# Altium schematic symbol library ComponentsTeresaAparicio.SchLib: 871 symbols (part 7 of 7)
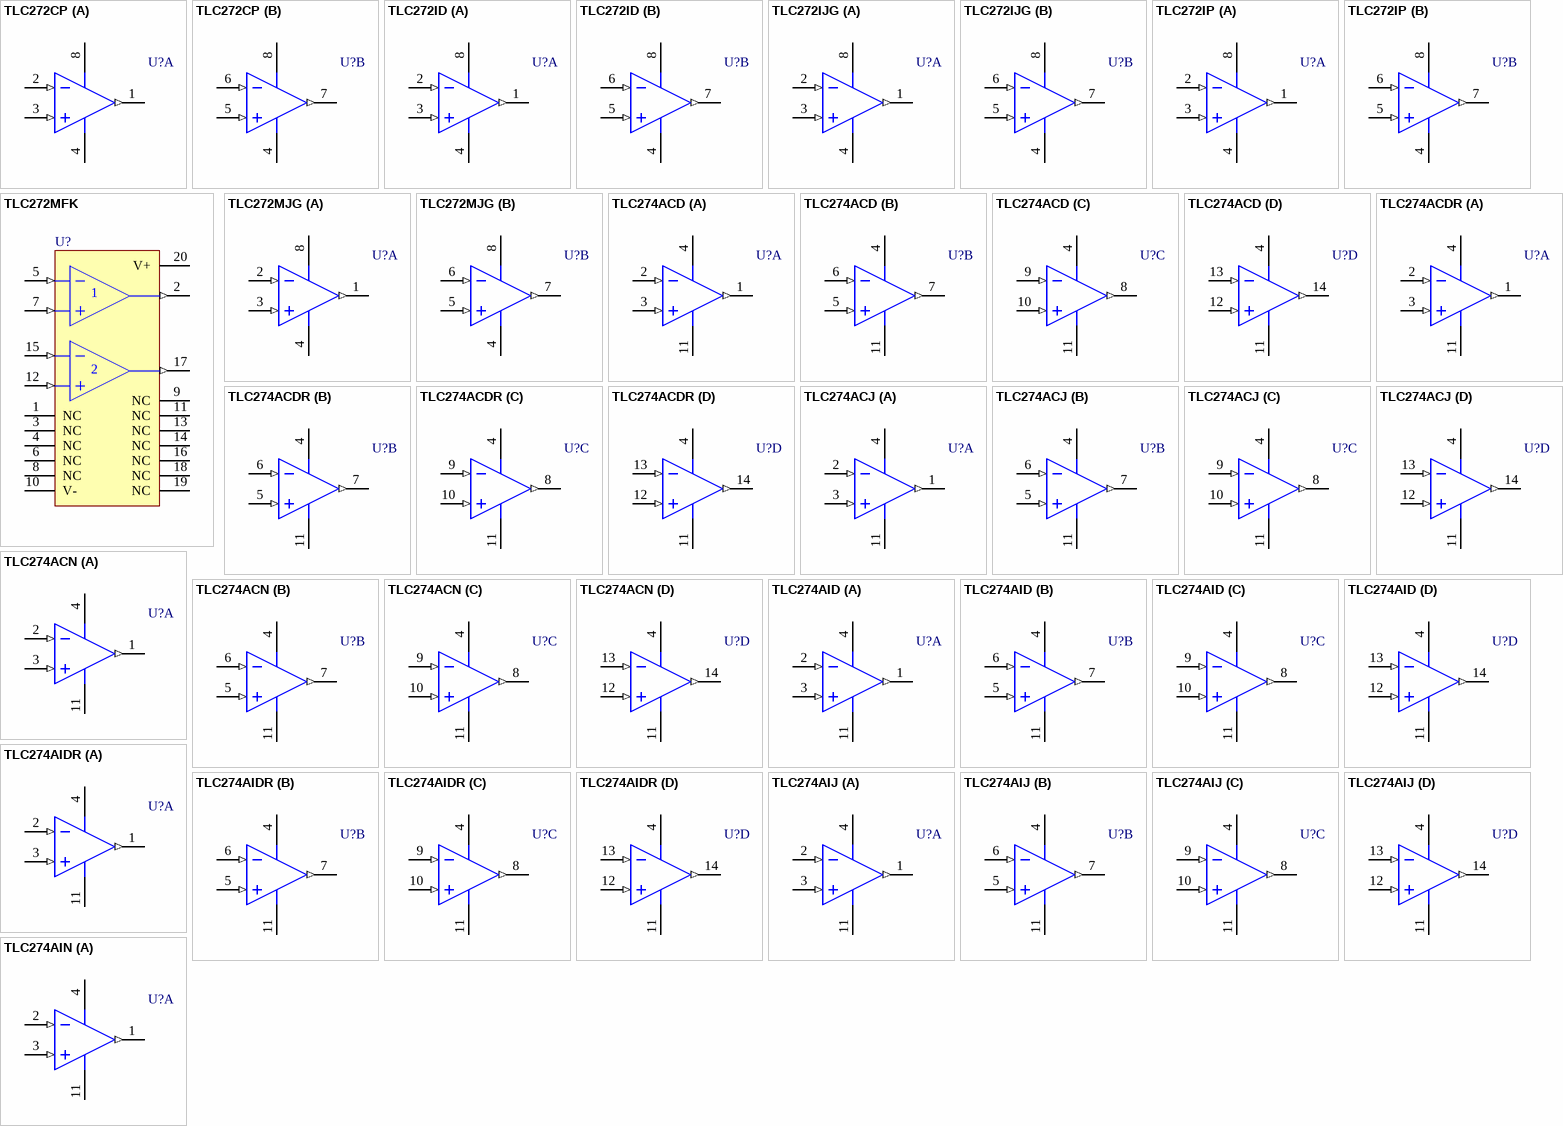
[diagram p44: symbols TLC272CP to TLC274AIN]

## TLC274AIJ
designator U?
LinCMOS Precision Quad Operational Amplifier
footprint J014 (DIP; 14 Leads; Row Spacing 7.62 mm; Pitch 2.54 mm)
3D model J014 (DIP; 14 Leads; Row Spacing 7.62 mm; Pitch 2.54 mm)
pins on every part: 4 V+ (power), 11 V- (power)
part A pins: 1 OUT (out), 2 IN- (in), 3 IN+ (in)
part B pins: 5 IN+ (in), 6 IN- (in), 7 OUT (out)
part C pins: 8 OUT (out), 9 IN- (in), 10 IN+ (in)
part D pins: 12 IN+ (in), 13 IN- (in), 14 OUT (out)

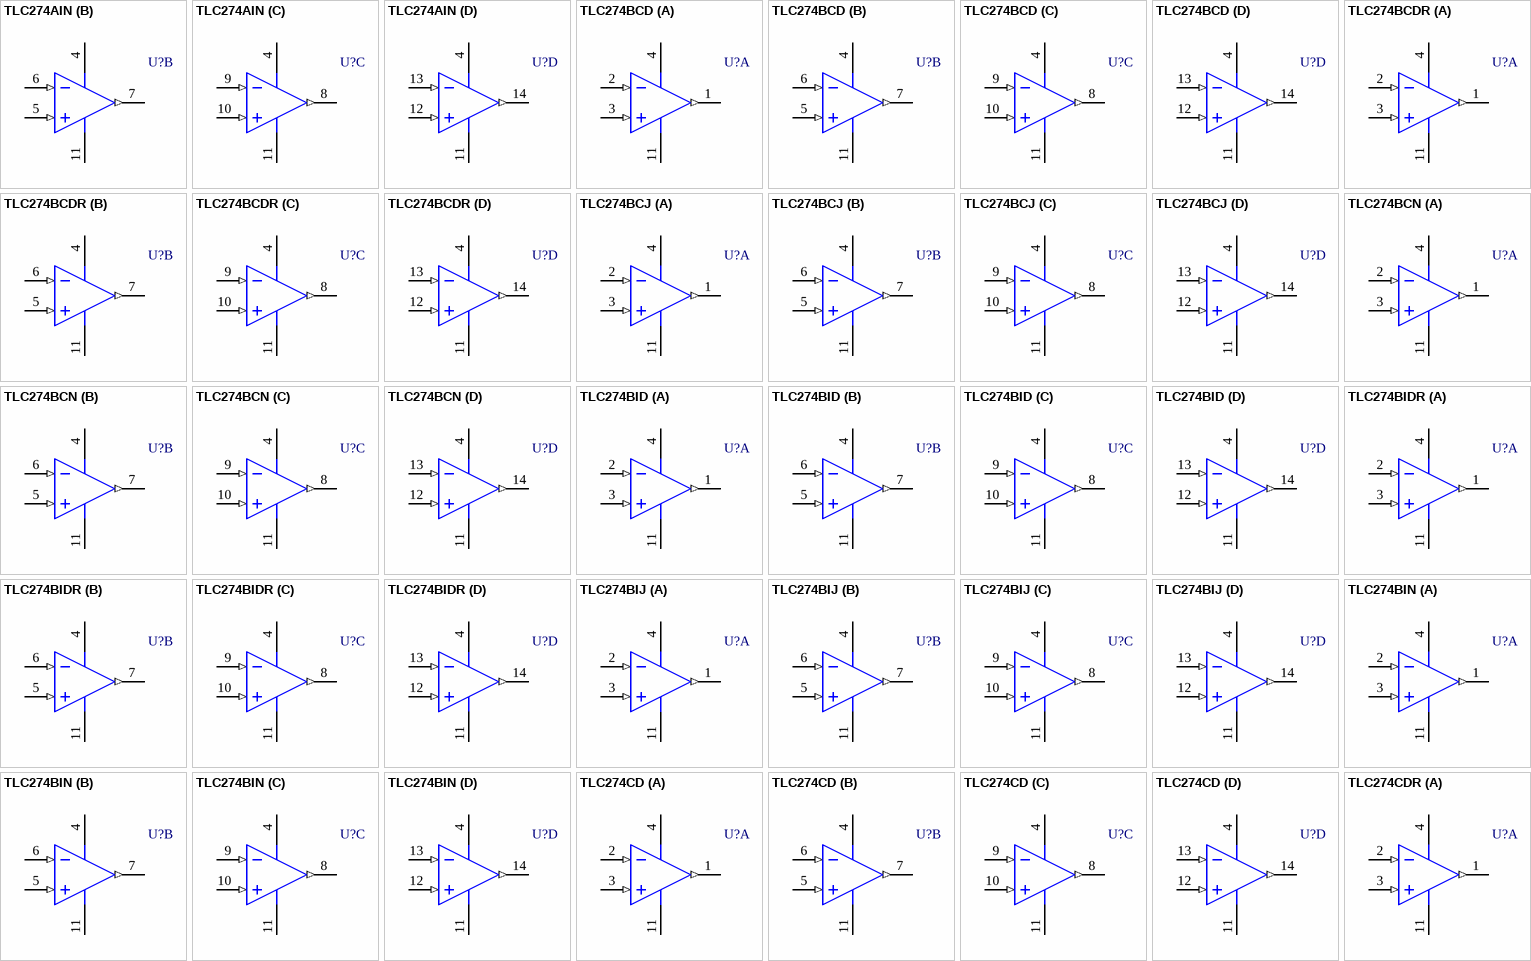
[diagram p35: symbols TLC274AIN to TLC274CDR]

## TLC274AIN
designator U?
LinCMOS Precision Quad Operational Amplifier
footprint N014 (DIP; 14 Leads; Row Spacing 7.62 mm; Pitch 2.54 mm)
3D model N014 (DIP; 14 Leads; Row Spacing 7.62 mm; Pitch 2.54 mm)
pins on every part: 4 V+ (power), 11 V- (power)
part A pins: 1 OUT (out), 2 IN- (in), 3 IN+ (in)
part B pins: 5 IN+ (in), 6 IN- (in), 7 OUT (out)
part C pins: 8 OUT (out), 9 IN- (in), 10 IN+ (in)
part D pins: 12 IN+ (in), 13 IN- (in), 14 OUT (out)

## TLC274BCD
designator U?
LinCMOS Precision Quad Operational Amplifier
footprint D014_N (SOIC, 14-Leads, Body 8.7x3.9mm, Pitch 1.27mm, IPC Medium Density)
footprint D014_L (SOIC, 14-Leads, Body 8.7x3.9mm, Pitch 1.27mm, IPC High Density)
footprint D014_M (SOIC, 14-Leads, Body 8.7x3.9mm, Pitch 1.27mm, IPC Low Density)
3D model D014 (14-Pin Small Outline Integrated Circuit 1.27 mm Pitch)
pins on every part: 4 V+ (power), 11 V- (power)
part A pins: 1 OUT (out), 2 IN- (in), 3 IN+ (in)
part B pins: 5 IN+ (in), 6 IN- (in), 7 OUT (out)
part C pins: 8 OUT (out), 9 IN- (in), 10 IN+ (in)
part D pins: 12 IN+ (in), 13 IN- (in), 14 OUT (out)

## TLC274BCDR
designator U?
LinCMOS Precision Quad Operational Amplifier
footprint D014_N (SOIC, 14-Leads, Body 8.7x3.9mm, Pitch 1.27mm, IPC Medium Density)
footprint D014_L (SOIC, 14-Leads, Body 8.7x3.9mm, Pitch 1.27mm, IPC High Density)
footprint D014_M (SOIC, 14-Leads, Body 8.7x3.9mm, Pitch 1.27mm, IPC Low Density)
3D model D014 (14-Pin Small Outline Integrated Circuit 1.27 mm Pitch)
pins on every part: 4 V+ (power), 11 V- (power)
part A pins: 1 OUT (out), 2 IN- (in), 3 IN+ (in)
part B pins: 5 IN+ (in), 6 IN- (in), 7 OUT (out)
part C pins: 8 OUT (out), 9 IN- (in), 10 IN+ (in)
part D pins: 12 IN+ (in), 13 IN- (in), 14 OUT (out)

## TLC274BCJ
designator U?
LinCMOS Precision Quad Operational Amplifier
footprint J014 (DIP; 14 Leads; Row Spacing 7.62 mm; Pitch 2.54 mm)
3D model J014 (DIP; 14 Leads; Row Spacing 7.62 mm; Pitch 2.54 mm)
pins on every part: 4 V+ (power), 11 V- (power)
part A pins: 1 OUT (out), 2 IN- (in), 3 IN+ (in)
part B pins: 5 IN+ (in), 6 IN- (in), 7 OUT (out)
part C pins: 8 OUT (out), 9 IN- (in), 10 IN+ (in)
part D pins: 12 IN+ (in), 13 IN- (in), 14 OUT (out)

## TLC274BCN
designator U?
LinCMOS Precision Quad Operational Amplifier
footprint N014 (DIP; 14 Leads; Row Spacing 7.62 mm; Pitch 2.54 mm)
3D model N014 (DIP; 14 Leads; Row Spacing 7.62 mm; Pitch 2.54 mm)
pins on every part: 4 V+ (power), 11 V- (power)
part A pins: 1 OUT (out), 2 IN- (in), 3 IN+ (in)
part B pins: 5 IN+ (in), 6 IN- (in), 7 OUT (out)
part C pins: 8 OUT (out), 9 IN- (in), 10 IN+ (in)
part D pins: 12 IN+ (in), 13 IN- (in), 14 OUT (out)

## TLC274BID
designator U?
LinCMOS Precision Quad Operational Amplifier
footprint D014_N (SOIC, 14-Leads, Body 8.7x3.9mm, Pitch 1.27mm, IPC Medium Density)
footprint D014_L (SOIC, 14-Leads, Body 8.7x3.9mm, Pitch 1.27mm, IPC High Density)
footprint D014_M (SOIC, 14-Leads, Body 8.7x3.9mm, Pitch 1.27mm, IPC Low Density)
3D model D014 (14-Pin Small Outline Integrated Circuit 1.27 mm Pitch)
pins on every part: 4 V+ (power), 11 V- (power)
part A pins: 1 OUT (out), 2 IN- (in), 3 IN+ (in)
part B pins: 5 IN+ (in), 6 IN- (in), 7 OUT (out)
part C pins: 8 OUT (out), 9 IN- (in), 10 IN+ (in)
part D pins: 12 IN+ (in), 13 IN- (in), 14 OUT (out)

## TLC274BIDR
designator U?
LinCMOS Precision Quad Operational Amplifier
footprint D014_N (SOIC, 14-Leads, Body 8.7x3.9mm, Pitch 1.27mm, IPC Medium Density)
footprint D014_L (SOIC, 14-Leads, Body 8.7x3.9mm, Pitch 1.27mm, IPC High Density)
footprint D014_M (SOIC, 14-Leads, Body 8.7x3.9mm, Pitch 1.27mm, IPC Low Density)
3D model D014 (14-Pin Small Outline Integrated Circuit 1.27 mm Pitch)
pins on every part: 4 V+ (power), 11 V- (power)
part A pins: 1 OUT (out), 2 IN- (in), 3 IN+ (in)
part B pins: 5 IN+ (in), 6 IN- (in), 7 OUT (out)
part C pins: 8 OUT (out), 9 IN- (in), 10 IN+ (in)
part D pins: 12 IN+ (in), 13 IN- (in), 14 OUT (out)

## TLC274BIJ
designator U?
LinCMOS Precision Quad Operational Amplifier
footprint J014 (DIP; 14 Leads; Row Spacing 7.62 mm; Pitch 2.54 mm)
3D model J014 (DIP; 14 Leads; Row Spacing 7.62 mm; Pitch 2.54 mm)
pins on every part: 4 V+ (power), 11 V- (power)
part A pins: 1 OUT (out), 2 IN- (in), 3 IN+ (in)
part B pins: 5 IN+ (in), 6 IN- (in), 7 OUT (out)
part C pins: 8 OUT (out), 9 IN- (in), 10 IN+ (in)
part D pins: 12 IN+ (in), 13 IN- (in), 14 OUT (out)

## TLC274BIN
designator U?
LinCMOS Precision Quad Operational Amplifier
footprint N014 (DIP; 14 Leads; Row Spacing 7.62 mm; Pitch 2.54 mm)
3D model N014 (DIP; 14 Leads; Row Spacing 7.62 mm; Pitch 2.54 mm)
pins on every part: 4 V+ (power), 11 V- (power)
part A pins: 1 OUT (out), 2 IN- (in), 3 IN+ (in)
part B pins: 5 IN+ (in), 6 IN- (in), 7 OUT (out)
part C pins: 8 OUT (out), 9 IN- (in), 10 IN+ (in)
part D pins: 12 IN+ (in), 13 IN- (in), 14 OUT (out)

## TLC274CD
designator U?
LinCMOS Precision Quad Operational Amplifier
footprint D014_N (SOIC, 14-Leads, Body 8.7x3.9mm, Pitch 1.27mm, IPC Medium Density)
footprint D014_L (SOIC, 14-Leads, Body 8.7x3.9mm, Pitch 1.27mm, IPC High Density)
footprint D014_M (SOIC, 14-Leads, Body 8.7x3.9mm, Pitch 1.27mm, IPC Low Density)
3D model D014 (14-Pin Small Outline Integrated Circuit 1.27 mm Pitch)
pins on every part: 4 V+ (power), 11 V- (power)
part A pins: 1 OUT (out), 2 IN- (in), 3 IN+ (in)
part B pins: 5 IN+ (in), 6 IN- (in), 7 OUT (out)
part C pins: 8 OUT (out), 9 IN- (in), 10 IN+ (in)
part D pins: 12 IN+ (in), 13 IN- (in), 14 OUT (out)

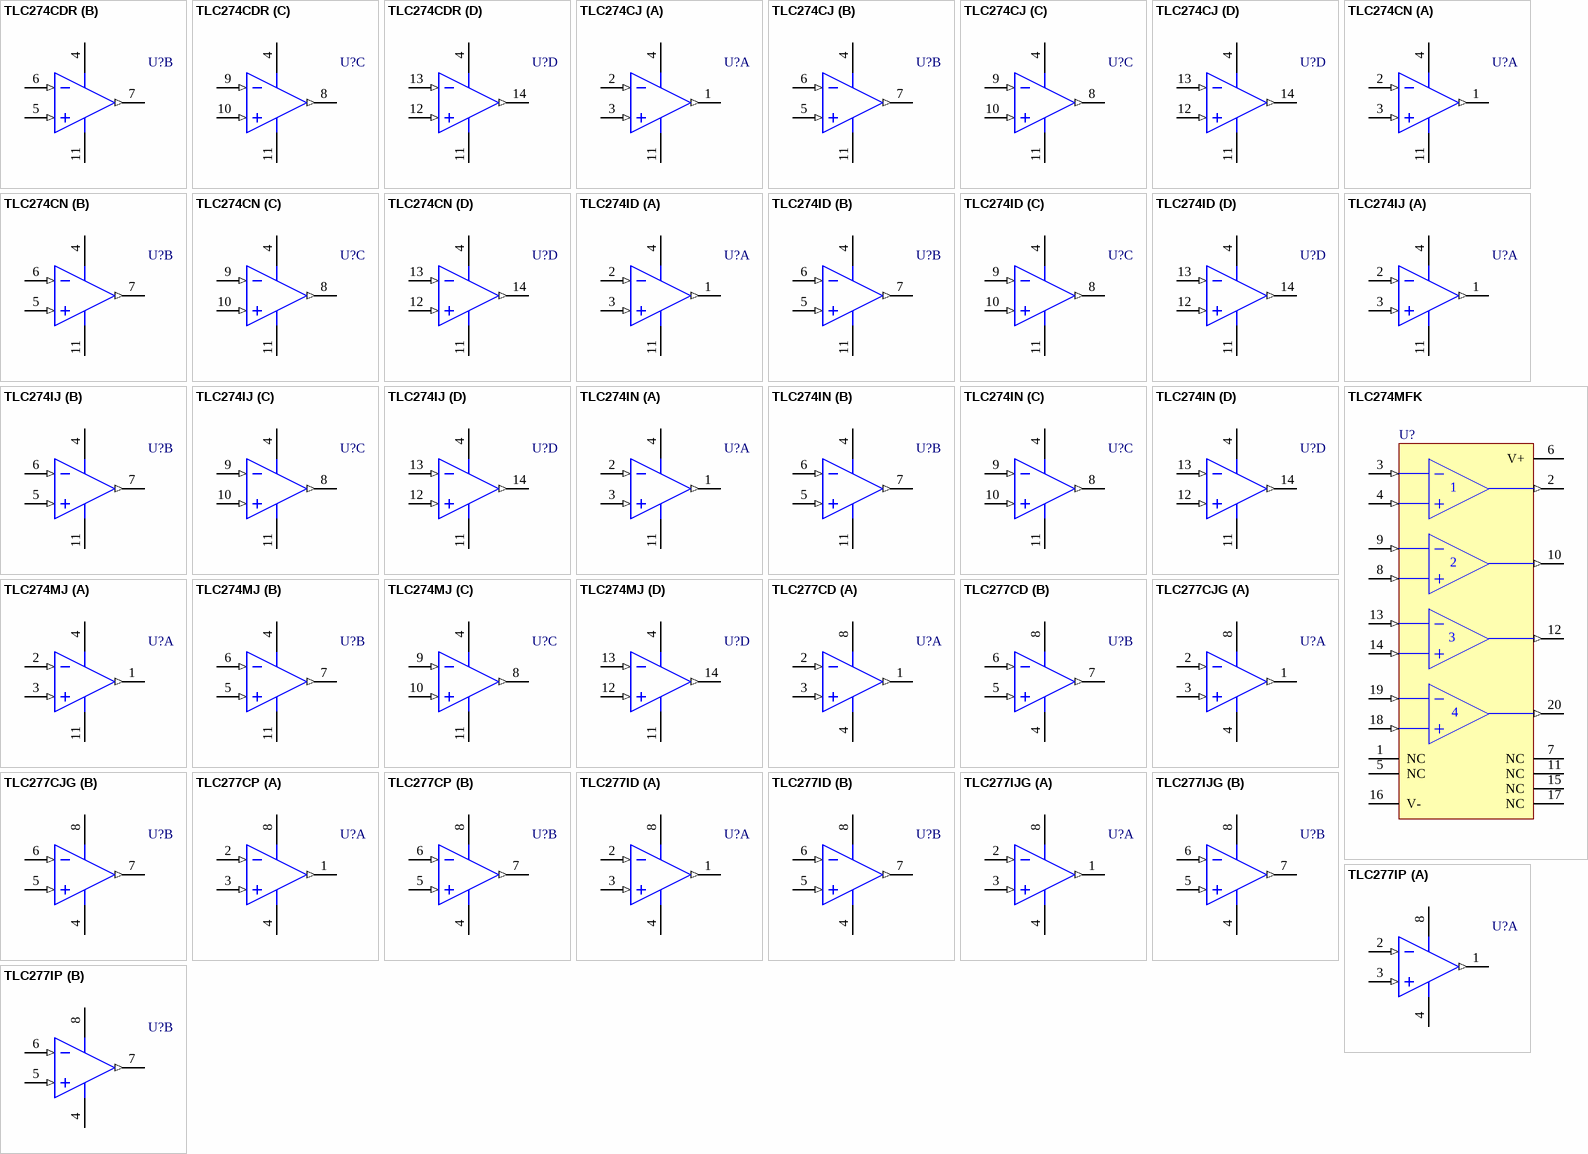
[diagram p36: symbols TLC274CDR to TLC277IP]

## TLC274CDR
designator U?
LinCMOS Precision Quad Operational Amplifier
footprint D014_N (SOIC, 14-Leads, Body 8.7x3.9mm, Pitch 1.27mm, IPC Medium Density)
footprint D014_L (SOIC, 14-Leads, Body 8.7x3.9mm, Pitch 1.27mm, IPC High Density)
footprint D014_M (SOIC, 14-Leads, Body 8.7x3.9mm, Pitch 1.27mm, IPC Low Density)
3D model D014 (14-Pin Small Outline Integrated Circuit 1.27 mm Pitch)
pins on every part: 4 V+ (power), 11 V- (power)
part A pins: 1 OUT (out), 2 IN- (in), 3 IN+ (in)
part B pins: 5 IN+ (in), 6 IN- (in), 7 OUT (out)
part C pins: 8 OUT (out), 9 IN- (in), 10 IN+ (in)
part D pins: 12 IN+ (in), 13 IN- (in), 14 OUT (out)

## TLC274CJ
designator U?
LinCMOS Precision Quad Operational Amplifier
footprint J014 (DIP; 14 Leads; Row Spacing 7.62 mm; Pitch 2.54 mm)
3D model J014 (DIP; 14 Leads; Row Spacing 7.62 mm; Pitch 2.54 mm)
pins on every part: 4 V+ (power), 11 V- (power)
part A pins: 1 OUT (out), 2 IN- (in), 3 IN+ (in)
part B pins: 5 IN+ (in), 6 IN- (in), 7 OUT (out)
part C pins: 8 OUT (out), 9 IN- (in), 10 IN+ (in)
part D pins: 12 IN+ (in), 13 IN- (in), 14 OUT (out)

## TLC274CN
designator U?
LinCMOS Precision Quad Operational Amplifier
footprint N014 (DIP; 14 Leads; Row Spacing 7.62 mm; Pitch 2.54 mm)
3D model N014 (DIP; 14 Leads; Row Spacing 7.62 mm; Pitch 2.54 mm)
pins on every part: 4 V+ (power), 11 V- (power)
part A pins: 1 OUT (out), 2 IN- (in), 3 IN+ (in)
part B pins: 5 IN+ (in), 6 IN- (in), 7 OUT (out)
part C pins: 8 OUT (out), 9 IN- (in), 10 IN+ (in)
part D pins: 12 IN+ (in), 13 IN- (in), 14 OUT (out)

## TLC274ID
designator U?
LinCMOS Precision Quad Operational Amplifier
footprint D014_N (SOIC, 14-Leads, Body 8.7x3.9mm, Pitch 1.27mm, IPC Medium Density)
footprint D014_L (SOIC, 14-Leads, Body 8.7x3.9mm, Pitch 1.27mm, IPC High Density)
footprint D014_M (SOIC, 14-Leads, Body 8.7x3.9mm, Pitch 1.27mm, IPC Low Density)
3D model D014 (14-Pin Small Outline Integrated Circuit 1.27 mm Pitch)
pins on every part: 4 V+ (power), 11 V- (power)
part A pins: 1 OUT (out), 2 IN- (in), 3 IN+ (in)
part B pins: 5 IN+ (in), 6 IN- (in), 7 OUT (out)
part C pins: 8 OUT (out), 9 IN- (in), 10 IN+ (in)
part D pins: 12 IN+ (in), 13 IN- (in), 14 OUT (out)

## TLC274IJ
designator U?
LinCMOS Precision Quad Operational Amplifier
footprint J014 (DIP; 14 Leads; Row Spacing 7.62 mm; Pitch 2.54 mm)
3D model J014 (DIP; 14 Leads; Row Spacing 7.62 mm; Pitch 2.54 mm)
pins on every part: 4 V+ (power), 11 V- (power)
part A pins: 1 OUT (out), 2 IN- (in), 3 IN+ (in)
part B pins: 5 IN+ (in), 6 IN- (in), 7 OUT (out)
part C pins: 8 OUT (out), 9 IN- (in), 10 IN+ (in)
part D pins: 12 IN+ (in), 13 IN- (in), 14 OUT (out)

## TLC274IN
designator U?
LinCMOS Precision Quad Operational Amplifier
footprint N014 (DIP; 14 Leads; Row Spacing 7.62 mm; Pitch 2.54 mm)
3D model N014 (DIP; 14 Leads; Row Spacing 7.62 mm; Pitch 2.54 mm)
pins on every part: 4 V+ (power), 11 V- (power)
part A pins: 1 OUT (out), 2 IN- (in), 3 IN+ (in)
part B pins: 5 IN+ (in), 6 IN- (in), 7 OUT (out)
part C pins: 8 OUT (out), 9 IN- (in), 10 IN+ (in)
part D pins: 12 IN+ (in), 13 IN- (in), 14 OUT (out)

## TLC274MFK
designator U?
LinCMOS Precision Quad Operational Amplifier; ComponentAvailability: Obsolete
footprint FK020 (Leadless Chip Carrier; 20 Terminals; Body 8.9 x 8.9 mm)
pins: 1 NC, 2 OUT (out), 3 IN- (in), 4 IN+ (in), 5 NC, 6 V+ (power), 7 NC, 8 IN+ (in), 9 IN- (in), 10 OUT (out), 11 NC, 12 OUT (out), 13 IN- (in), 14 IN+ (in), 15 NC, 16 V- (power), 17 NC, 18 IN+ (in), 19 IN- (in), 20 OUT (out)

## TLC274MJ
designator U?
LinCMOS Precision Quad Operational Amplifier; ComponentAvailability: Obsolete
footprint J014 (DIP; 14 Leads; Row Spacing 7.62 mm; Pitch 2.54 mm)
3D model J014 (DIP; 14 Leads; Row Spacing 7.62 mm; Pitch 2.54 mm)
pins on every part: 4 V+ (power), 11 V- (power)
part A pins: 1 OUT (out), 2 IN- (in), 3 IN+ (in)
part B pins: 5 IN+ (in), 6 IN- (in), 7 OUT (out)
part C pins: 8 OUT (out), 9 IN- (in), 10 IN+ (in)
part D pins: 12 IN+ (in), 13 IN- (in), 14 OUT (out)

## TLC277CD
designator U?
LinCMOS Precision Dual Operational Amplifier
footprint D008_L (SOIC, 8-Leads, Body 4.9x3.9mm, Pitch 1.27mm, IPC High Density)
footprint D008_M (SOIC, 8-Leads, Body 4.9x3.9mm, Pitch 1.27mm, IPC Low Density)
footprint D008_M (SOIC, 8-Leads, Body 4.9x3.9mm, Pitch 1.27mm, IPC Low Density)
3D model D008 (8-Pin Small Outline Integrated Circuit 1.27 mm Pitch)
pins on every part: 4 GND (power), 8 VDD (power)
part A pins: 1 OUT (out), 2 IN- (in), 3 IN+ (in)
part B pins: 5 IN+ (in), 6 IN- (in), 7 OUT (out)

## TLC277CJG
designator U?
LinCMOS Precision Dual Operational Amplifier
footprint JG008 (DIP; 8 Leads; Row Spacing 7.62 mm; Pitch 2.54 mm)
3D model JG008 (DIP; 8 Leads; Row Spacing 7.62 mm; Pitch 2.54 mm)
pins on every part: 4 GND (power), 8 VDD (power)
part A pins: 1 OUT (out), 2 IN- (in), 3 IN+ (in)
part B pins: 5 IN+ (in), 6 IN- (in), 7 OUT (out)

## TLC277CP
designator U?
LinCMOS Precision Dual Operational Amplifier
footprint P008 (DIP; 8 Leads; Row Spacing 7.62 mm; Pitch 2.54 mm)
3D model P008 (DIP; 8 Leads; Row Spacing 7.62 mm; Pitch 2.54 mm)
pins on every part: 4 GND (power), 8 VDD (power)
part A pins: 1 OUT (out), 2 IN- (in), 3 IN+ (in)
part B pins: 5 IN+ (in), 6 IN- (in), 7 OUT (out)

## TLC277ID
designator U?
LinCMOS Precision Dual Operational Amplifier
footprint D008_L (SOIC, 8-Leads, Body 4.9x3.9mm, Pitch 1.27mm, IPC High Density)
footprint D008_M (SOIC, 8-Leads, Body 4.9x3.9mm, Pitch 1.27mm, IPC Low Density)
footprint D008_M (SOIC, 8-Leads, Body 4.9x3.9mm, Pitch 1.27mm, IPC Low Density)
3D model D008 (8-Pin Small Outline Integrated Circuit 1.27 mm Pitch)
pins on every part: 4 GND (power), 8 VDD (power)
part A pins: 1 OUT (out), 2 IN- (in), 3 IN+ (in)
part B pins: 5 IN+ (in), 6 IN- (in), 7 OUT (out)

## TLC277IJG
designator U?
LinCMOS Precision Dual Operational Amplifier
footprint JG008 (DIP; 8 Leads; Row Spacing 7.62 mm; Pitch 2.54 mm)
3D model JG008 (DIP; 8 Leads; Row Spacing 7.62 mm; Pitch 2.54 mm)
pins on every part: 4 GND (power), 8 VDD (power)
part A pins: 1 OUT (out), 2 IN- (in), 3 IN+ (in)
part B pins: 5 IN+ (in), 6 IN- (in), 7 OUT (out)

## TLC277IP
designator U?
LinCMOS Precision Dual Operational Amplifier
footprint P008 (DIP; 8 Leads; Row Spacing 7.62 mm; Pitch 2.54 mm)
3D model P008 (DIP; 8 Leads; Row Spacing 7.62 mm; Pitch 2.54 mm)
pins on every part: 4 GND (power), 8 VDD (power)
part A pins: 1 OUT (out), 2 IN- (in), 3 IN+ (in)
part B pins: 5 IN+ (in), 6 IN- (in), 7 OUT (out)

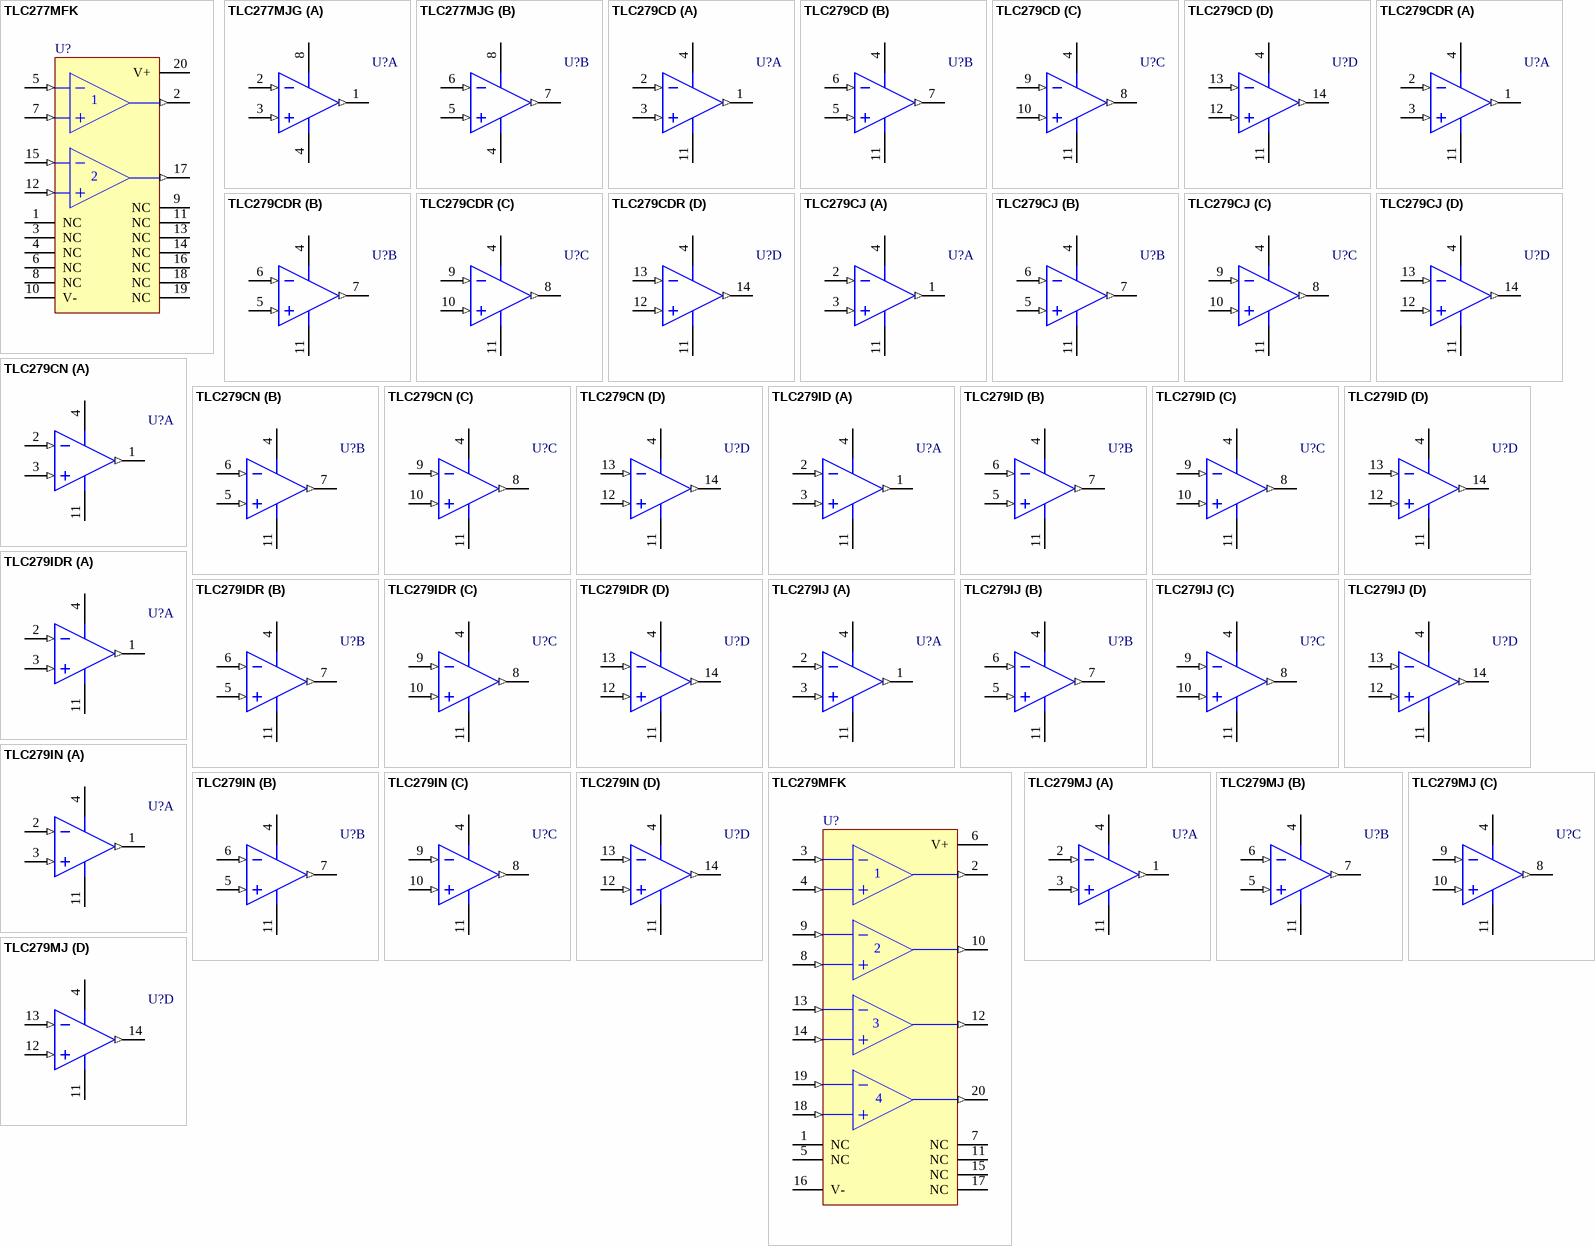
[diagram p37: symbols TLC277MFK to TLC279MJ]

## TLC277MFK
designator U?
LinCMOS Precision Quad Operational Amplifier; ComponentAvailability: Obsolete
footprint FK020 (Leadless Chip Carrier; 20 Terminals; Body 8.9 x 8.9 mm)
pins: 1 NC, 2 OUT (out), 3 NC, 4 NC, 5 IN- (in), 6 NC, 7 IN+ (in), 8 NC, 9 NC, 10 V- (power), 11 NC, 12 IN+ (in), 13 NC, 14 NC, 15 IN- (in), 16 NC, 17 OUT (out), 18 NC, 19 NC, 20 V+ (power)

## TLC277MJG
designator U?
LinCMOS Precision Dual Operational Amplifier; ComponentAvailability: Obsolete
footprint JG008 (DIP; 8 Leads; Row Spacing 7.62 mm; Pitch 2.54 mm)
3D model JG008 (DIP; 8 Leads; Row Spacing 7.62 mm; Pitch 2.54 mm)
pins on every part: 4 GND (power), 8 VDD (power)
part A pins: 1 OUT (out), 2 IN- (in), 3 IN+ (in)
part B pins: 5 IN+ (in), 6 IN- (in), 7 OUT (out)

## TLC279CD
designator U?
LinCMOS Precision Quad Operational Amplifier
footprint D014_N (SOIC, 14-Leads, Body 8.7x3.9mm, Pitch 1.27mm, IPC Medium Density)
footprint D014_L (SOIC, 14-Leads, Body 8.7x3.9mm, Pitch 1.27mm, IPC High Density)
footprint D014_M (SOIC, 14-Leads, Body 8.7x3.9mm, Pitch 1.27mm, IPC Low Density)
3D model D014 (14-Pin Small Outline Integrated Circuit 1.27 mm Pitch)
pins on every part: 4 V+ (power), 11 V- (power)
part A pins: 1 OUT (out), 2 IN- (in), 3 IN+ (in)
part B pins: 5 IN+ (in), 6 IN- (in), 7 OUT (out)
part C pins: 8 OUT (out), 9 IN- (in), 10 IN+ (in)
part D pins: 12 IN+ (in), 13 IN- (in), 14 OUT (out)

## TLC279CDR
designator U?
LinCMOS Precision Quad Operational Amplifier
footprint D014_N (SOIC, 14-Leads, Body 8.7x3.9mm, Pitch 1.27mm, IPC Medium Density)
footprint D014_L (SOIC, 14-Leads, Body 8.7x3.9mm, Pitch 1.27mm, IPC High Density)
footprint D014_M (SOIC, 14-Leads, Body 8.7x3.9mm, Pitch 1.27mm, IPC Low Density)
3D model D014 (14-Pin Small Outline Integrated Circuit 1.27 mm Pitch)
pins on every part: 4 V+ (power), 11 V- (power)
part A pins: 1 OUT (out), 2 IN- (in), 3 IN+ (in)
part B pins: 5 IN+ (in), 6 IN- (in), 7 OUT (out)
part C pins: 8 OUT (out), 9 IN- (in), 10 IN+ (in)
part D pins: 12 IN+ (in), 13 IN- (in), 14 OUT (out)

## TLC279CJ
designator U?
LinCMOS Precision Quad Operational Amplifier
footprint J014 (DIP; 14 Leads; Row Spacing 7.62 mm; Pitch 2.54 mm)
3D model J014 (DIP; 14 Leads; Row Spacing 7.62 mm; Pitch 2.54 mm)
pins on every part: 4 V+ (power), 11 V- (power)
part A pins: 1 OUT (out), 2 IN- (in), 3 IN+ (in)
part B pins: 5 IN+ (in), 6 IN- (in), 7 OUT (out)
part C pins: 8 OUT (out), 9 IN- (in), 10 IN+ (in)
part D pins: 12 IN+ (in), 13 IN- (in), 14 OUT (out)

## TLC279CN
designator U?
LinCMOS Precision Quad Operational Amplifier
footprint N014 (DIP; 14 Leads; Row Spacing 7.62 mm; Pitch 2.54 mm)
3D model N014 (DIP; 14 Leads; Row Spacing 7.62 mm; Pitch 2.54 mm)
pins on every part: 4 V+ (power), 11 V- (power)
part A pins: 1 OUT (out), 2 IN- (in), 3 IN+ (in)
part B pins: 5 IN+ (in), 6 IN- (in), 7 OUT (out)
part C pins: 8 OUT (out), 9 IN- (in), 10 IN+ (in)
part D pins: 12 IN+ (in), 13 IN- (in), 14 OUT (out)

## TLC279ID
designator U?
LinCMOS Precision Quad Operational Amplifier
footprint D014_N (SOIC, 14-Leads, Body 8.7x3.9mm, Pitch 1.27mm, IPC Medium Density)
footprint D014_L (SOIC, 14-Leads, Body 8.7x3.9mm, Pitch 1.27mm, IPC High Density)
footprint D014_M (SOIC, 14-Leads, Body 8.7x3.9mm, Pitch 1.27mm, IPC Low Density)
3D model D014 (14-Pin Small Outline Integrated Circuit 1.27 mm Pitch)
pins on every part: 4 V+ (power), 11 V- (power)
part A pins: 1 OUT (out), 2 IN- (in), 3 IN+ (in)
part B pins: 5 IN+ (in), 6 IN- (in), 7 OUT (out)
part C pins: 8 OUT (out), 9 IN- (in), 10 IN+ (in)
part D pins: 12 IN+ (in), 13 IN- (in), 14 OUT (out)

## TLC279IDR
designator U?
LinCMOS Precision Quad Operational Amplifier
footprint D014_N (SOIC, 14-Leads, Body 8.7x3.9mm, Pitch 1.27mm, IPC Medium Density)
footprint D014_L (SOIC, 14-Leads, Body 8.7x3.9mm, Pitch 1.27mm, IPC High Density)
footprint D014_M (SOIC, 14-Leads, Body 8.7x3.9mm, Pitch 1.27mm, IPC Low Density)
3D model D014 (14-Pin Small Outline Integrated Circuit 1.27 mm Pitch)
pins on every part: 4 V+ (power), 11 V- (power)
part A pins: 1 OUT (out), 2 IN- (in), 3 IN+ (in)
part B pins: 5 IN+ (in), 6 IN- (in), 7 OUT (out)
part C pins: 8 OUT (out), 9 IN- (in), 10 IN+ (in)
part D pins: 12 IN+ (in), 13 IN- (in), 14 OUT (out)

## TLC279IJ
designator U?
LinCMOS Precision Quad Operational Amplifier
footprint J014 (DIP; 14 Leads; Row Spacing 7.62 mm; Pitch 2.54 mm)
3D model J014 (DIP; 14 Leads; Row Spacing 7.62 mm; Pitch 2.54 mm)
pins on every part: 4 V+ (power), 11 V- (power)
part A pins: 1 OUT (out), 2 IN- (in), 3 IN+ (in)
part B pins: 5 IN+ (in), 6 IN- (in), 7 OUT (out)
part C pins: 8 OUT (out), 9 IN- (in), 10 IN+ (in)
part D pins: 12 IN+ (in), 13 IN- (in), 14 OUT (out)

## TLC279IN
designator U?
LinCMOS Precision Quad Operational Amplifier
footprint N014 (DIP; 14 Leads; Row Spacing 7.62 mm; Pitch 2.54 mm)
3D model N014 (DIP; 14 Leads; Row Spacing 7.62 mm; Pitch 2.54 mm)
pins on every part: 4 V+ (power), 11 V- (power)
part A pins: 1 OUT (out), 2 IN- (in), 3 IN+ (in)
part B pins: 5 IN+ (in), 6 IN- (in), 7 OUT (out)
part C pins: 8 OUT (out), 9 IN- (in), 10 IN+ (in)
part D pins: 12 IN+ (in), 13 IN- (in), 14 OUT (out)

## TLC279MFK
designator U?
LinCMOS Precision Quad Operational Amplifier; ComponentAvailability: Obsolete
footprint FK020 (Leadless Chip Carrier; 20 Terminals; Body 8.9 x 8.9 mm)
pins: 1 NC, 2 OUT (out), 3 IN- (in), 4 IN+ (in), 5 NC, 6 V+ (power), 7 NC, 8 IN+ (in), 9 IN- (in), 10 OUT (out), 11 NC, 12 OUT (out), 13 IN- (in), 14 IN+ (in), 15 NC, 16 V- (power), 17 NC, 18 IN+ (in), 19 IN- (in), 20 OUT (out)

## TLC279MJ
designator U?
LinCMOS Precision Quad Operational Amplifier; ComponentAvailability: Obsolete
footprint J014 (DIP; 14 Leads; Row Spacing 7.62 mm; Pitch 2.54 mm)
3D model J014 (DIP; 14 Leads; Row Spacing 7.62 mm; Pitch 2.54 mm)
pins on every part: 4 V+ (power), 11 V- (power)
part A pins: 1 OUT (out), 2 IN- (in), 3 IN+ (in)
part B pins: 5 IN+ (in), 6 IN- (in), 7 OUT (out)
part C pins: 8 OUT (out), 9 IN- (in), 10 IN+ (in)
part D pins: 12 IN+ (in), 13 IN- (in), 14 OUT (out)

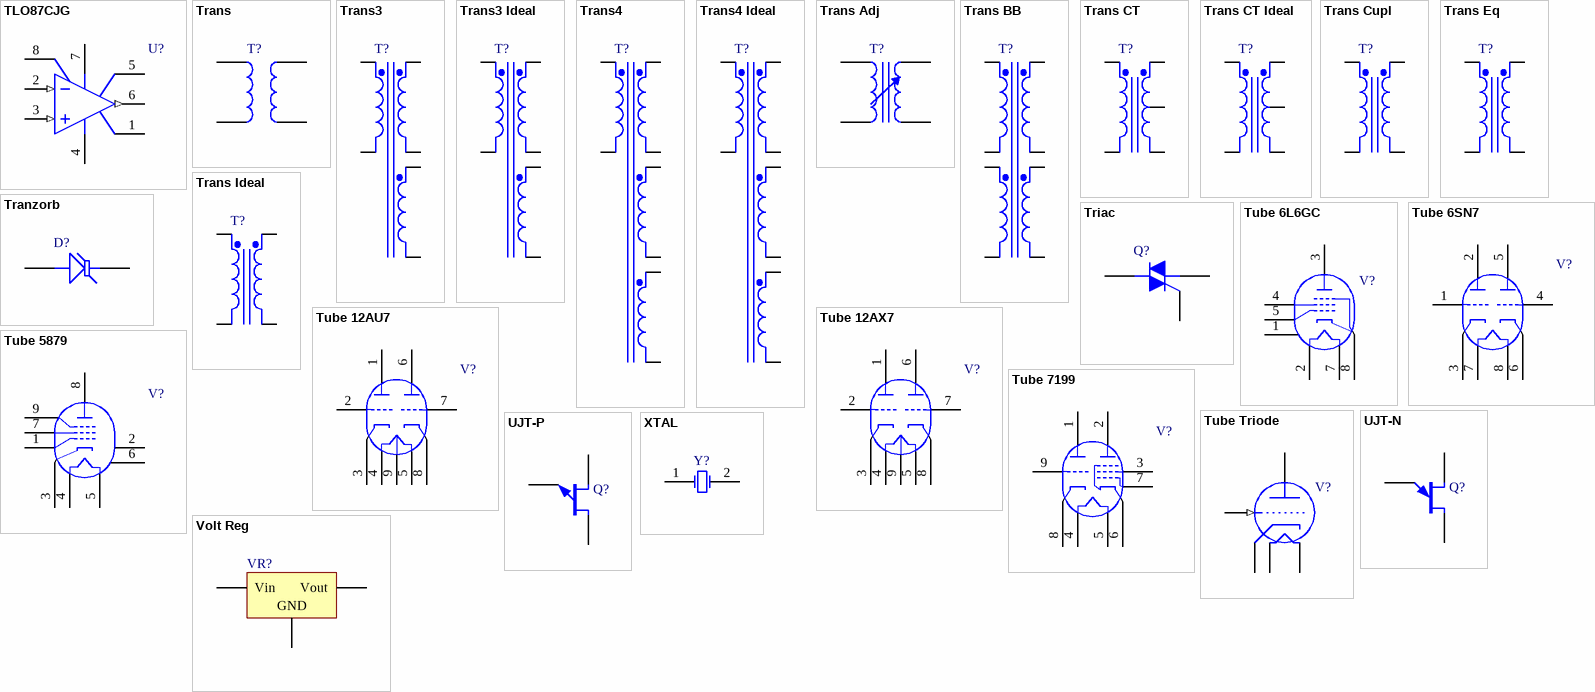
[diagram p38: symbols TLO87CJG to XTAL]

## TLO87CJG
designator U?
JFET-Input Operational Amplifier
footprint JG008 (DIP; 8 Leads; Row Spacing 7.62 mm; Pitch 2.54 mm)
3D model JG008 (DIP; 8 Leads; Row Spacing 7.62 mm; Pitch 2.54 mm)
pins: 1 OS N1, 2 IN- (in), 3 IN+ (in), 4 V- (power), 5 OS N2, 6 OUT (out), 7 V+ (power), 8 NC

## Trans
designator T?
Transformer
footprint TRANS (Transformer; 4 Leads)
simulation model TRANSFORMER (Transformer)
pins: 1, 2, 3, 4

## Trans3
designator T?
Three-winding Transformer (Non-Ideal); Sim Note: Enter the turns ratios, Core loss resistance, Magnetising Reactance, Leakage Reactances and Resistances referred to the primary side into the parameter fields.
footprint TRF_6 (Transformer; 6 Leads)
simulation model NI3WTRANS (Spice Subcircuit)
pins: 1 Pri+, 2 Pri-, 3 Sec1+, 4 Sec1-, 5 Sec2+, 6 Sec2-

## Trans3 Ideal
designator T?
Three-winding Transformer (Ideal)
footprint TRF_6 (Transformer; 6 Leads)
simulation model IDEAL3W (Spice Subcircuit)
pins: 1 Pri+, 2 Pri-, 3 Sec1+, 4 Sec1-, 5 Sec2+, 6 Sec2-

## Trans4
designator T?
Four-winding Transformer (Non-Ideal); Sim Note: Enter the turns ratios, Core loss resistance, Magnetising Reactance, Leakage Reactances and Resistances referred to the primary side into the parameter fields.
footprint TRF_8 (Transformer; 8 Leads)
simulation model NI4WTRANS (Spice Subcircuit)
pins: 1 Pri+, 2 Pri-, 3 Sec1+, 4 Sec1-, 5 Sec2+, 6 Sec2-, 7 Sec3+, 8 Sec3-

## Trans4 Ideal
designator T?
Four-winding Transformer (Ideal)
footprint TRF_8 (Transformer; 8 Leads)
simulation model IDEAL4W (Spice Subcircuit)
pins: 1 Pri+, 2 Pri-, 3 Sec1+, 4 Sec1-, 5 Sec2+, 6 Sec2-, 7 Sec3+, 8 Sec3-

## Trans Adj
designator T?
Variable Transformer
footprint TRF_4 (Transformer; 4 Leads)
simulation model TRANSFORMER (Transformer)
pins: 1, 2, 3, 4

## Trans BB
designator T?
Buck-boost Transformer (Ideal)
footprint TRF_8 (Transformer; 8 Leads)
simulation model IDEAL4W (Spice Subcircuit)
pins: 1 Pri1+, 2 Pri1-, 3 Pri2+, 4 Pri2-, 5 Sec1+, 6 Sec1-, 7 Sec2+, 8 Sec2-

## Trans CT
designator T?
Center-Tapped Transformer (Coupled Inductor Model)
footprint TRF_5 (Transformer; 5 Leads)
simulation model TRANSFORMER (Transformer)
pins: 1 Pri+, 2 Pri-, 3 Sec+, 4 SecCT, 5 Sec-

## Trans CT Ideal
designator T?
Center-Tapped Transformer (Ideal)
footprint TRF_5 (Transformer; 5 Leads)
simulation model IDEALTRANSCT (Spice Subcircuit)
pins: 1 Pri+, 2 Pri-, 3 Sec+, 4 SecCT, 5 Sec-

## Trans Cupl
designator T?
Transformer (Coupled Inductor Model)
footprint TRF_4 (Transformer; 4 Leads)
simulation model TRANSFORMER (Transformer)
pins: 1 Pri+, 2 Pri-, 3 Sec+, 4 Sec-

## Trans Eq
designator T?
Transformer (Equivalent Circuit Model)
footprint TRF_4 (Transformer; 4 Leads)
simulation model TRANS (Spice Subcircuit)
pins: 1 Pri+, 2 Pri-, 3 Sec+, 4 Sec-

## Trans Ideal
designator T?
Transformer (Ideal)
footprint TRF_4 (Transformer; 4 Leads)
simulation model IDEALTRANS (Spice Subcircuit)
pins: 1 Pri+, 2 Pri-, 3 Sec+, 4 Sec-

## Tranzorb
designator D?
Transient Voltage Suppression (TVS) Diode
footprint DO-7 (Diode, Axial; Body 7 x 2.7 mm (LxDia. max), Lead Dia. 0.53 mm (max))
pins: 1 A, 2 K

## Triac
designator Q?
Silicon Bidirectional Triode Thyristor; Note: Pin 2 is electrically connected to Pin 4 (TAB)
footprint 369-03 (TO, Thru-Hole, Vertical, Heatsink Mounted; 3 In-Line Leads; Pitch 2.28 mm)
simulation model MAC15A8 (Spice Subcircuit)
pins: 1 M1, 2 M2, 3 G

## Tube 6L6GC
designator V?
Beam Power Pentode; Note: Pin 6 is omitted from the tube package, Pin 1 is Not Connected
footprint VTUBE-7 (Vacuum Tube; 7 Leads)
simulation model 6L6GC (Spice Subcircuit)
pins: 1 NC, 2 H, 3 PT, 4 GT2, 5 GT1, 7 H, 8 G3, KT

## Tube 6SN7
designator V?
Medium Mu Dual Triode
footprint VTUBE-8 (Vacuum Tube; 8 Leads)
simulation model 6SN7 (Spice Subcircuit)
pins: 1 GT1, 2 PT1, 3 KT1, 4 GT2, 5 PT2, 6 KT2, 7 H, 8 H

## Tube 12AU7
designator V?
Medium Mu Dual Triode
footprint VTUBE-9 (Vacuum Tube; 9 Leads)
simulation model 12AU7 (Spice Subcircuit)
pins: 1 PT1, 2 GT1, 3 KT1, 4 H, 5 H, 6 PT2, 7 GT2, 8 KT2, 9 HM

## Tube 12AX7
designator V?
High Mu Dual Triode
footprint VTUBE-9 (Vacuum Tube; 9 Leads)
simulation model 12AX7 (Spice Subcircuit)
pins: 1 PT1, 2 GT1, 3 KT1, 4 H, 5 H, 6 PT2, 7 GT2, 8 KT2, 9 HM

## Tube 5879
designator V?
Sharp Cutoff Pentode; Note: Pins 2 and 6 are not connected.
footprint VTUBE-9 (Vacuum Tube; 9 Leads)
pins: 1 GT1, 2 NC, 3 KT, 4 H, 5 H, 6 NC, 7 GT2, 8 PT, 9 GT3

## Tube 7199
designator V?
Medium Mu Triode and Sharp Cutoff Pentode
footprint VTUBE-9 (Vacuum Tube; 9 Leads)
simulation model 7199 (Spice Subcircuit)
pins: 1 PT1, 2 PT2, 3 GT2, 4 H, 5 H, 6 KT2, 7 GT3, 8 KT1, 9 GT1

## Tube Triode
designator V?
Thyratron
footprint VTUBE-5 (Vacuum Tube; 5 Leads)
pins: 1 GRID (in), 2 PLATE, 3 CATHODE, 4 FILAMENT1, 5 FILAMENT2

## UJT-N
designator Q?
Unijunction Transistor with N-Type Base
footprint TO-39 (Can; 3 Leads; Pin Circle Dia. 5.08 mm; Lead Dia. 0.48 mm (max))
simulation model NUJT (Spice Subcircuit)
pins: 1 E, 2 B1, 3 B2

## UJT-P
designator Q?
Unijunction Transistor with P-Type Base
footprint TO-205AF (Can; 3 Leads; Pin Circle Dia. 5.08 mm; Lead Dia. 0.53 mm (max))
pins: 1 E, 2 B1, 3 B2

## Volt Reg
designator VR?
Voltage Regulator
footprint D2PAK_N (D2-PAK, 4-Leads, Body 8.8x10.4mm, Pitch 2.54mm, Lead Span 15.1mm, IPC Medium Density)
footprint D2PAK_L (D2-PAK, 4-Leads, Body 8.8x10.4mm, Pitch 2.54mm, Lead Span 15.1mm, IPC High Density)
footprint D2PAK_M (D2-PAK, 4-Leads, Body 8.8x10.4mm, Pitch 2.54mm, Lead Span 15.1mm, IPC Low Density)
pins: 1 Vin, 2 GND, 3 Vout

## XTAL
designator Y?
Crystal Oscillator
footprint R38 (Crystal, Thru-Hole; 2 Leads; Body 3.1 x 8.2 mm (Dia.xH))
simulation model XTAL (Spice Subcircuit)
pins: 1 OSC1, 2 OSC2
